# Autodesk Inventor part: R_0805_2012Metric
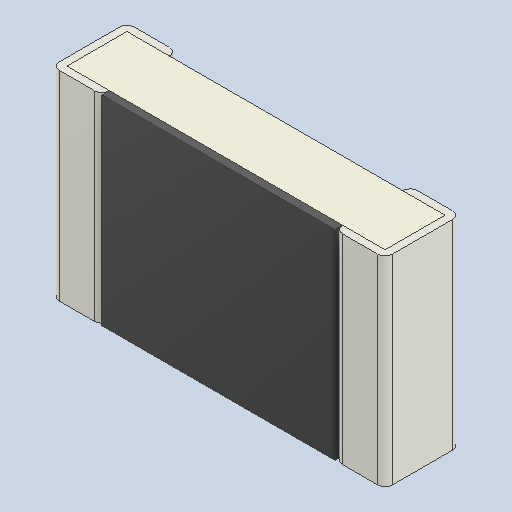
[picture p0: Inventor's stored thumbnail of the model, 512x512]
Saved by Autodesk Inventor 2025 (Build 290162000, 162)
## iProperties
Created: 2026-09
Part Number: R_0805_2012Metric
Material: Generic
Document SubType Name: Modeling
Designer: Leonardo
Density: 1 g/cm^3
Appearance: Default
Author: Leonardo
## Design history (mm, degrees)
feature "Base1"
body "Solid1"
